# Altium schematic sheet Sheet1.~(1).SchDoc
size A
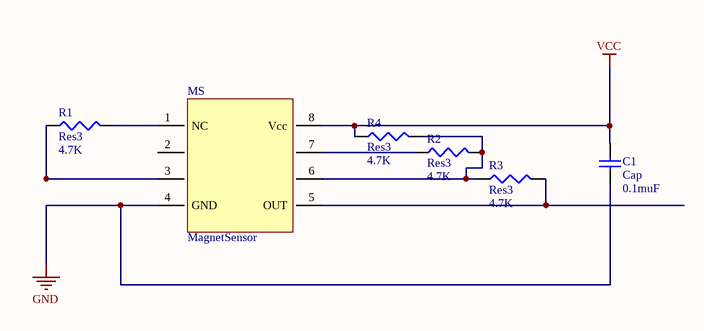
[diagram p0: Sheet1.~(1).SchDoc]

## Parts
C1  Cap  value 0.1muF  [RAD-0.3]
MS  MagnetSensor  [AD22151]
R1  Res3  value 4.7K  [12Z-2010]
R2  Res3  value 4.7K  [12Z-2010]
R3  Res3  value 4.7K  [12Z-2010]
R4  Res3  value 4.7K  [12Z-2010]

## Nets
GND: C1.1 MS.4(GND)
VCC: C1.2 MS.8(Vcc) R4.1
NetMS_1: MS.1(NC) R1.2
NetMS_3: MS.3 R1.1
NetMS_5: MS.5(OUT) R3.2
NetMS_6: MS.6 R2.2 R3.1 R4.2
NetMS_7: MS.7 R2.1

Not connected (* = marked no-connect by the designer): MS 2

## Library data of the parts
C1 = Cap: Capacitor
MS = Component_1
R1-R4 = Res3: Resistor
